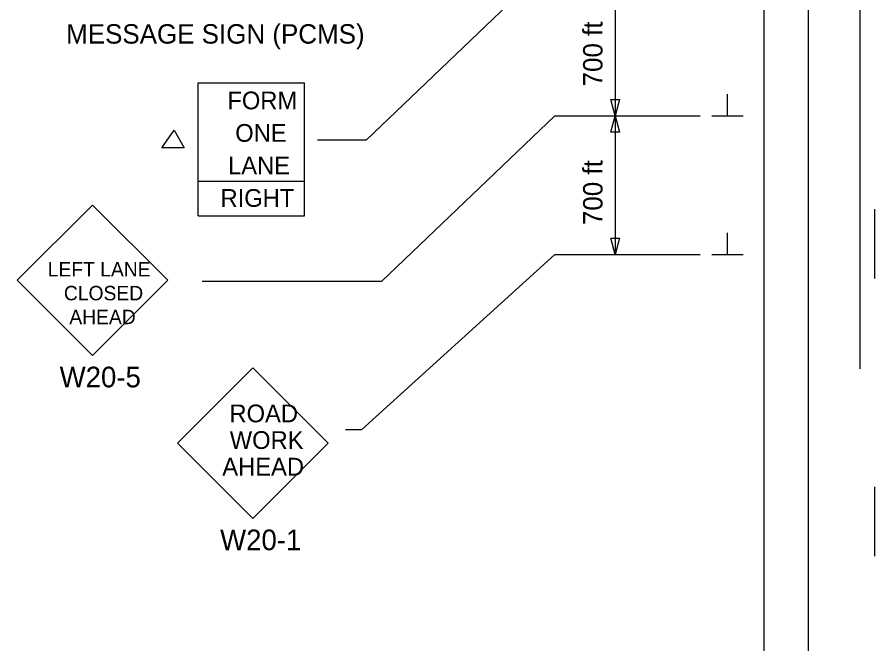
# Model space of a CAD drawing. Extents: x 15261 to 18126, y 1908 to 6555.
# Drawn here: x 16306.9 to 16616.4, y 2305.6 to 2534 of the extents above; entities that cross this region are included whole.
import ezdxf

# ---------------------------------------------------------------- set-up
doc = ezdxf.new("R2010")
doc.units = 0
for name, color, linetype in [('ALI_LEGAL_EX', 7, 'Continuous'), ('Level 3', 7, 'Continuous'), ('PAVT_EDGE_EX', 7, 'Continuous'), ('TRAFFIC_SIGNS_PR', 7, 'Continuous'), ('TYPICAL_TEXT_DIMEN_PR', 7, 'Continuous')]:
    doc.layers.add(name, color=color, linetype=linetype)

msp = doc.modelspace()

# ---------------------------------------------------------------- linework, layer by layer
at = {"layer": 'ALI_LEGAL_EX'}
msp.add_line((16610.98, 3236.46), (16610.98, 2407.28), dxfattribs=at)
for points in [[(16616.35, 2439.74), (16616.35, 2464.74)], [(16616.35, 2339.74), (16616.35, 2364.74)]]:
    msp.add_lwpolyline(points, dxfattribs=at)
at = {"layer": 'Level 3'}
msp.add_line((16431.12, 2385.18), (16425.43, 2385.18), dxfattribs=at)
at = {"layer": 'PAVT_EDGE_EX'}
for p, q in [((16576.35, 3138.78), (16576.35, 2305.55)), ((16592.35, 3138.78), (16592.35, 2305.55))]:
    msp.add_line(p, q, dxfattribs=at)
at = {"layer": 'TRAFFIC_SIGNS_PR'}
for p, q in [((16372.27, 2462.43), (16372.27, 2510.39)), ((16372.27, 2510.39), (16410.63, 2510.39)), ((16410.63, 2462.43), (16410.63, 2510.39)), ((16372.27, 2474.84), (16410.63, 2474.84)), ((16334.09, 2466.29), (16306.94, 2439.14)), ((16361.24, 2439.14), (16334.09, 2466.29)), ((16372.27, 2462.43), (16410.63, 2462.43)), ((16306.94, 2439.14), (16334.09, 2411.99)), ((16334.09, 2411.99), (16361.24, 2439.14)), ((16391.98, 2407.57), (16364.83, 2380.42)), ((16419.14, 2380.42), (16391.98, 2407.57)), ((16364.83, 2380.42), (16391.98, 2353.26)), ((16391.98, 2353.26), (16419.14, 2380.42))]:
    msp.add_line(p, q, dxfattribs=at)
at = {"layer": 'TYPICAL_TEXT_DIMEN_PR'}
for p, q in [((16494.38, 2548.48), (16432.89, 2489.71)), ((16522.62, 2548.48), (16522.62, 2498.48)), ((16563.23, 2498.48), (16563.23, 2506.26)), ((16522.62, 2498.48), (16521.05, 2504.34)), ((16521.05, 2504.34), (16522.62, 2504.34)), ((16522.62, 2504.34), (16524.2, 2504.34)), ((16524.2, 2504.34), (16522.62, 2498.48)), ((16500.94, 2498.48), (16438.49, 2438.78)), ((16500.94, 2498.48), (16553.35, 2498.48)), ((16521.05, 2492.61), (16522.62, 2498.48)), ((16522.62, 2498.48), (16522.62, 2448.48)), ((16522.62, 2498.48), (16524.2, 2492.61)), ((16557.6, 2498.48), (16568.85, 2498.48)), ((16522.62, 2492.61), (16521.05, 2492.61)), ((16524.2, 2492.61), (16522.62, 2492.61)), ((16432.89, 2489.71), (16415.24, 2489.71)), ((16522.62, 2448.48), (16521.05, 2454.34)), ((16521.05, 2454.34), (16522.62, 2454.34)), ((16522.62, 2454.34), (16524.2, 2454.34)), ((16524.2, 2454.34), (16522.62, 2448.48)), ((16563.23, 2448.48), (16563.23, 2456.26)), ((16500.94, 2448.48), (16431.12, 2385.18)), ((16500.94, 2448.48), (16553.35, 2448.48)), ((16557.6, 2448.48), (16568.85, 2448.48)), ((16373.73, 2438.78), (16438.49, 2438.78))]:
    msp.add_line(p, q, dxfattribs=at)
msp.add_lwpolyline([(16359.17, 2486.96), (16363.53, 2493.26), (16367.24, 2486.96)], close=True, dxfattribs=at)

# ---------------------------------------------------------------- texts
at = {"layer": 'TRAFFIC_SIGNS_PR'}
for s, height, p in [('MESSAGE SIGN (PCMS)', 7, (16324.62, 2524.48)), ('FORM', 6.394, (16382.79, 2500.8)), ('ONE', 6.394, (16385.61, 2489.08)), ('LANE', 6.394, (16383.03, 2477.35)), ('RIGHT', 6.394, (16380.31, 2465.63)), ('LEFT LANE', 5.2, (16317.97, 2440.53)), ('CLOSED', 5.2, (16323.8, 2431.93)), ('AHEAD', 5.2, (16325.75, 2423.33)), ('W20-5', 7.44, (16322.26, 2400.55)), ('ROAD', 6.4, (16383.53, 2387.95)), ('WORK', 6.4, (16383.63, 2378.35)), ('AHEAD', 6.4, (16380.94, 2368.75)), ('W20-1', 7.44, (16380.15, 2341.83))]:
    msp.add_text(s, height=height, dxfattribs=at).set_placement(p)
at = {"layer": 'TYPICAL_TEXT_DIMEN_PR'}
for p in [(16518.1, 2509.05), (16518.1, 2459.05)]:
    msp.add_text('700 ft', height=7, rotation=90, dxfattribs=at).set_placement(p)

doc.saveas('drawing.dxf')
